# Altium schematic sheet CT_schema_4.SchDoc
size 288 x 169 mm
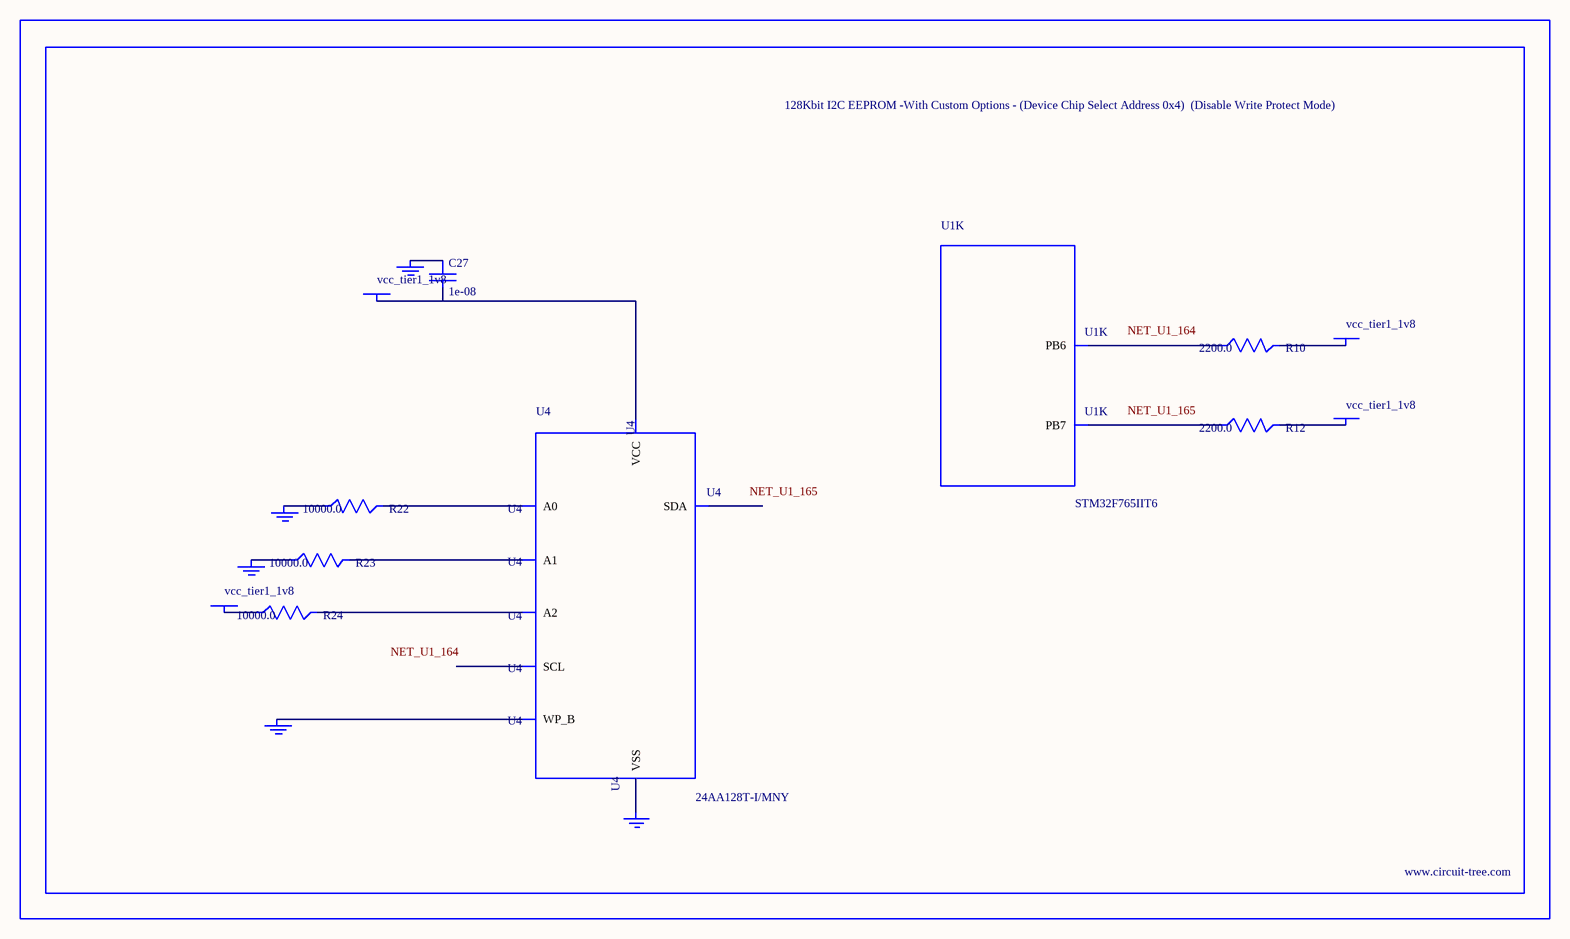
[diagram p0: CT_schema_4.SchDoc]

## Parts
BORDER3  (no value)
C27  1e-08  [C0402]
GND_INSTANCE_3_0  (no value)
GND_INSTANCE_3_1  (no value)
GND_INSTANCE_3_2  (no value)
GND_INSTANCE_3_3  (no value)
GND_INSTANCE_3_4  (no value)
POWER_INSTANCE_3_0  vcc_tier1_1v8
POWER_INSTANCE_3_1  vcc_tier1_1v8
POWER_INSTANCE_3_2  vcc_tier1_1v8
POWER_INSTANCE_3_3  vcc_tier1_1v8
R10  2200.0  [R0603]
R12  2200.0  [R0603]
R22  10000.0  [R0603]
R23  10000.0  [R0603]
R24  10000.0  [R0603]
U1  STM32F765IIT6  [LQFP176]  (part K of 12)
U4  24AA128T-I/MNY  [TDFN-8/6MM]

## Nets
NetC27_1: C27.1 GND_INSTANCE_3_3.0(GND)
NetC27_2: C27.2 POWER_INSTANCE_3_1.0(PWR) U4.8(VCC)
NetGND_INSTANCE_3_0_0: GND_INSTANCE_3_0.0(GND) R22.1
NetGND_INSTANCE_3_1_0: GND_INSTANCE_3_1.0(GND) R23.1
NetGND_INSTANCE_3_2_0: GND_INSTANCE_3_2.0(GND) U4.7(WP_B)
NetGND_INSTANCE_3_4_0: GND_INSTANCE_3_4.0(GND) U4.4(VSS)
NetPOWER_INSTANCE_3_0_0: POWER_INSTANCE_3_0.0(PWR) R24.1
NetPOWER_INSTANCE_3_2_0: POWER_INSTANCE_3_2.0(PWR) R10.2
NetPOWER_INSTANCE_3_3_0: POWER_INSTANCE_3_3.0(PWR) R12.2
NetR10_1: R10.1 U1.164(PB6)
NetR12_1: R12.1 U1.165(PB7)
NetR22_2: R22.2 U4.1(A0)
NetR23_2: R23.2 U4.2(A1)
NetR24_2: R24.2 U4.3(A2)

Not connected (* = marked no-connect by the designer): U4 5(SDA) 6(SCL)

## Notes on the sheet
- Labels drawn without touching a wire or pin: NET_U1_164, NET_U1_165

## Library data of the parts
BORDER3 = BORDER_PAGE3
C27 = C0402C103K3RAC
GND_INSTANCE_3_0-GND_INSTANCE_3_4 = GND
POWER_INSTANCE_3_0-POWER_INSTANCE_3_3 = PWR
R10 R12 = RC0603JR-072K2L
R22-R24 = RC0603JR-0710KL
